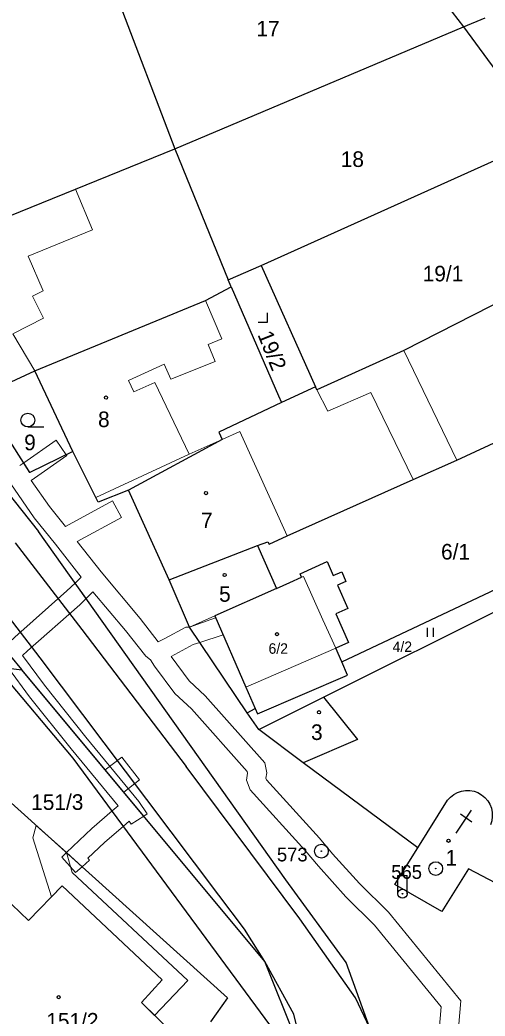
# Model space of a CAD drawing. Extents: x -606517 to -602431, y -1183120 to -1179397.
# Drawn here: x -605471.6 to -605420.9, y -1180870.1 to -1180761.6 of the extents above; entities that cross this region are included whole.
import ezdxf
from ezdxf.enums import TextEntityAlignment as Align

# ---------------------------------------------------------------- set-up
doc = ezdxf.new("R2010")
doc.units = 0
doc.header["$LTSCALE"] = 0.68
for name, color, linetype, lineweight in [('1', 7, 'Continuous', 25), ('13', 7, 'Continuous', 13), ('3', 7, 'Continuous', 25), ('4', 7, 'Continuous', 13), ('5', 7, 'Continuous', 25), ('6', 7, 'Continuous', 25), ('8', 7, 'Continuous', 25)]:
    doc.layers.add(name, color=color, linetype=linetype, lineweight=lineweight)
doc.layers.add('2', color=7, linetype='Continuous')

msp = doc.modelspace()

# ---------------------------------------------------------------- linework, layer by layer
at = {"layer": '1'}
for p, q in [((-605436.71, -1180744.63), (-605423.26, -1180762.37)), ((-605462.45, -1180755.29), (-605454.69, -1180775.65)), ((-605454.69, -1180775.65), (-605423.26, -1180762.37)), ((-605423.26, -1180762.37), (-605420.9, -1180761.38)), ((-605423.26, -1180762.37), (-605414.36, -1180774.43)), ((-605445.31, -1180788.34), (-605414.36, -1180774.43)), ((-605465.54, -1180780.05), (-605454.69, -1180775.65)), ((-605454.69, -1180775.65), (-605448.88, -1180789.92)), ((-605478.02, -1180785.08), (-605465.54, -1180780.05)), ((-605448.88, -1180789.92), (-605445.31, -1180788.34)), ((-605445.31, -1180788.34), (-605439.39, -1180801.56)), ((-605448.57, -1180790.68), (-605448.88, -1180789.92)), ((-605451.36, -1180792.16), (-605448.57, -1180790.68)), ((-605448.57, -1180790.68), (-605443.4, -1180802.52)), ((-605416.71, -1180790.96), (-605429.75, -1180797.61)), ((-605489.67, -1180792.12), (-605469.57, -1180817.3)), ((-605469.96, -1180799.8), (-605451.36, -1180792.16)), ((-605429.75, -1180797.61), (-605439.24, -1180801.88)), ((-605475.85, -1180802.53), (-605469.96, -1180799.8)), ((-605465.83, -1180808.61), (-605469.96, -1180799.8)), ((-605470.51, -1180810.87), (-605475.85, -1180802.53)), ((-605443.4, -1180802.52), (-605443.07, -1180803.28)), ((-605439.39, -1180801.56), (-605443.07, -1180803.28)), ((-605439.24, -1180801.88), (-605439.39, -1180801.56)), ((-605443.07, -1180803.28), (-605449.91, -1180806.48)), ((-605423.96, -1180809.53), (-605412.45, -1180804.22)), ((-605449.91, -1180806.48), (-605449.54, -1180807.29)), ((-605449.54, -1180807.29), (-605459.74, -1180812.8)), ((-605465.83, -1180808.61), (-605470.51, -1180810.87)), ((-605463.31, -1180813.61), (-605465.83, -1180808.61)), ((-605428.74, -1180811.65), (-605423.96, -1180809.53)), ((-605442.47, -1180817.78), (-605428.74, -1180811.65)), ((-605459.74, -1180812.8), (-605463.06, -1180814.11)), ((-605455.32, -1180822.57), (-605459.74, -1180812.8)), ((-605463.06, -1180814.11), (-605463.31, -1180813.61)), ((-605442.62, -1180855.26), (-605469.57, -1180817.3)), ((-605436.52, -1180831.49), (-605406.17, -1180817.2)), ((-605472.09, -1180818.55), (-605464.82, -1180827.99)), ((-605445.7, -1180818.84), (-605444.55, -1180818.43)), ((-605444.55, -1180818.43), (-605444.43, -1180818.69)), ((-605444.43, -1180818.69), (-605442.47, -1180817.78)), ((-605455.32, -1180822.57), (-605445.7, -1180818.84)), ((-605445.7, -1180818.84), (-605443.62, -1180823.51)), ((-605438.49, -1180835.36), (-605405.86, -1180819.07)), ((-605441.05, -1180821.91), (-605438.11, -1180820.59)), ((-605438.11, -1180820.59), (-605437.44, -1180822.11)), ((-605469.39, -1180831.07), (-605476.42, -1180821.94)), ((-605440.88, -1180822.29), (-605441.05, -1180821.91)), ((-605437.44, -1180822.11), (-605436.52, -1180821.7)), ((-605436.52, -1180821.7), (-605436.05, -1180822.75)), ((-605453.1, -1180827.72), (-605455.32, -1180822.57)), ((-605443.62, -1180823.51), (-605442.17, -1180822.87)), ((-605442.17, -1180822.87), (-605440.88, -1180822.29)), ((-605436.05, -1180822.75), (-605436.97, -1180823.16)), ((-605443.62, -1180823.51), (-605450.35, -1180826.5)), ((-605436.97, -1180823.16), (-605435.84, -1180825.69)), ((-605435.84, -1180825.69), (-605437.17, -1180826.28)), ((-605437.17, -1180826.28), (-605435.77, -1180829.41)), ((-605450.35, -1180826.5), (-605446.95, -1180834.26)), ((-605464.82, -1180827.99), (-605453.47, -1180842.89)), ((-605446.81, -1180837.04), (-605453.1, -1180827.72)), ((-605471.38, -1180832.34), (-605473.82, -1180829.44)), ((-605435.77, -1180829.41), (-605437.15, -1180830.03)), ((-605436.52, -1180831.49), (-605437.15, -1180830.03)), ((-605457.76, -1180846.51), (-605469.39, -1180831.07)), ((-605435.88, -1180832.95), (-605436.52, -1180831.49)), ((-605474.17, -1180832.04), (-605471.36, -1180832.38)), ((-605465.77, -1180841.98), (-605474.17, -1180832.04)), ((-605471.36, -1180832.38), (-605471.38, -1180832.34)), ((-605444.9, -1180864.13), (-605471.36, -1180832.38)), ((-605445.69, -1180837.15), (-605435.88, -1180832.95)), ((-605446.95, -1180834.26), (-605445.95, -1180836.57)), ((-605445.56, -1180838.87), (-605438.49, -1180835.36)), ((-605438.49, -1180835.36), (-605434.81, -1180839.95)), ((-605446.81, -1180837.04), (-605445.95, -1180836.57)), ((-605445.56, -1180838.87), (-605446.81, -1180837.04)), ((-605445.95, -1180836.57), (-605445.69, -1180837.15)), ((-605481.78, -1180838.53), (-605448.98, -1180868.1)), ((-605440.72, -1180842.51), (-605445.56, -1180838.87)), ((-605434.81, -1180839.95), (-605440.72, -1180842.51)), ((-605442.62, -1180873.35), (-605465.77, -1180841.98)), ((-605428.22, -1180851.75), (-605440.72, -1180842.51)), ((-605441.08, -1180859.5), (-605453.47, -1180842.89)), ((-605449.91, -1180856.92), (-605457.76, -1180846.51)), ((-605428.22, -1180851.75), (-605424.98, -1180846.58)), ((-605430.72, -1180855.76), (-605428.22, -1180851.75)), ((-605422.7, -1180854.04), (-605425.61, -1180858.7)), ((-605419.72, -1180855.62), (-605422.7, -1180854.04)), ((-605436.03, -1180864.23), (-605442.62, -1180855.26)), ((-605470.64, -1180859.68), (-605466.97, -1180855.88)), ((-605466.97, -1180855.88), (-605456.08, -1180866.15)), ((-605425.61, -1180858.7), (-605430.72, -1180855.76)), ((-605447.12, -1180860.63), (-605449.91, -1180856.92)), ((-605472.46, -1180857.94), (-605470.64, -1180859.68)), ((-605435.03, -1180868.09), (-605441.08, -1180859.5)), ((-605444.9, -1180864.13), (-605447.12, -1180860.63)), ((-605441.2, -1180873.28), (-605444.9, -1180864.13)), ((-605441.75, -1180869.86), (-605444.9, -1180864.13)), ((-605433.45, -1180871.4), (-605436.03, -1180864.23)), ((-605456.08, -1180866.15), (-605458.34, -1180868.59)), ((-605458.34, -1180868.59), (-605455.01, -1180871.88)), ((-605448.98, -1180868.1), (-605450.8, -1180870.69)), ((-605433.45, -1180871.4), (-605435.03, -1180868.09)), ((-605440.96, -1180872.97), (-605441.75, -1180869.86))]:
    msp.add_line(p, q, dxfattribs=at)
msp.add_lwpolyline([(-605424.98, -1180846.58), (-605424.673, -1180846.235), (-605424.311, -1180845.948), (-605423.907, -1180845.726), (-605423.47, -1180845.576), (-605423.014, -1180845.502), (-605422.552, -1180845.507), (-605422.098, -1180845.589), (-605421.665, -1180845.748), (-605421.264, -1180845.978), (-605420.909, -1180846.272), (-605420.608, -1180846.623), (-605420.371, -1180847.019), (-605420.205, -1180847.45), (-605420.114, -1180847.902), (-605420.102, -1180848.364), (-605420.168, -1180848.821), (-605420.31, -1180849.26)], dxfattribs=at)
at = {"layer": '13'}
for points in [[(-605471.17, -1180809.84), (-605470.51, -1180810.87), (-605466.53, -1180808.95), (-605467.63, -1180807.36)], [(-605465.58, -1180822.92), (-605466.46, -1180823.79), (-605472.15, -1180828.8), (-605473.37, -1180829.98), (-605471.38, -1180832.34), (-605471.36, -1180832.38), (-605458.09, -1180848.3), (-605457.73, -1180848.07), (-605458.62, -1180846.7), (-605464.39, -1180839.69), (-605468.92, -1180834.04), (-605471.29, -1180830.82), (-605470.75, -1180830.3), (-605465.06, -1180825.29), (-605464.37, -1180824.62)], [(-605453.1, -1180827.72), (-605451.97, -1180829.39), (-605449.44, -1180828.58), (-605450.26, -1180826.71)], [(-605474.01, -1180830.6), (-605472.83, -1180832.2), (-605470.54, -1180835.3), (-605465.99, -1180840.99), (-605460.88, -1180847.19), (-605461.52, -1180847.74), (-605463.73, -1180849.65), (-605466.52, -1180852.28), (-605464.81, -1180853.83), (-605463.99, -1180853.1), (-605464.19, -1180852.88), (-605462.37, -1180851.17), (-605460.3, -1180849.39), (-605459.68, -1180848.86), (-605459.47, -1180849.19), (-605458.09, -1180848.3), (-605471.36, -1180832.38), (-605471.38, -1180832.34), (-605473.37, -1180829.98)], [(-605462.29, -1180843.27), (-605460.27, -1180845.68), (-605458.55, -1180844.36), (-605460.48, -1180841.88)], [(-605466.52, -1180852.28), (-605469.81, -1180849.32), (-605470.17, -1180850.66), (-605468.13, -1180857.08), (-605466.97, -1180855.88), (-605456.08, -1180866.15), (-605458.34, -1180868.59), (-605456.91, -1180870), (-605453.27, -1180866.22), (-605465.88, -1180854.43)], [(-605464.81, -1180853.83), (-605466.52, -1180852.28), (-605467.03, -1180852.76), (-605465.51, -1180854.46)]]:
    msp.add_lwpolyline(points, close=True, dxfattribs=at)
for points in [[(-605424.05, -1180874.33), (-605423.55, -1180868.42), (-605431.43, -1180858.78), (-605434.58, -1180855.66), (-605437.52, -1180852.41), (-605438.95, -1180850.69), (-605444.7, -1180844.36), (-605444.77, -1180844.17), (-605444.67, -1180843.58), (-605444.91, -1180842.49), (-605451.4, -1180835.19), (-605453.15, -1180833.58), (-605455.11, -1180830.93), (-605452.7, -1180829.62), (-605451.97, -1180829.39), (-605453.1, -1180827.72), (-605453.52, -1180827.74), (-605455.79, -1180828.98), (-605456.5, -1180829.32), (-605458.48, -1180826.79), (-605462.73, -1180821.72), (-605465.33, -1180818.39), (-605460.53, -1180815.77), (-605461.51, -1180813.97), (-605466.62, -1180816.76), (-605468.37, -1180814.59), (-605470.34, -1180811.74), (-605466.47, -1180809.04), (-605466.53, -1180808.95), (-605470.51, -1180810.87), (-605471.17, -1180809.84), (-605471.59, -1180810.13)], [(-605472.57, -1180812.13), (-605470.03, -1180815.81), (-605467.71, -1180818.69), (-605464.92, -1180822.27), (-605465.58, -1180822.92), (-605464.37, -1180824.62), (-605463.62, -1180823.88), (-605460.08, -1180828.09), (-605457.88, -1180830.89), (-605457.36, -1180831.3), (-605456.9, -1180831.97), (-605454.69, -1180834.96), (-605452.88, -1180836.63), (-605446.81, -1180843.46), (-605446.77, -1180843.64), (-605446.89, -1180844.39), (-605446.48, -1180845.46), (-605440.49, -1180852.05), (-605439.06, -1180853.77), (-605436.06, -1180857.08), (-605432.95, -1180860.18)], [(-605432.95, -1180860.18), (-605425.67, -1180869.08), (-605426.14, -1180874.57)]]:
    msp.add_lwpolyline(points, dxfattribs=at)
at = {"layer": '3'}
for p, q in [((-605470.723, -1180805.93), (-605468.973, -1180805.93)), ((-605427.172, -1180828.79), (-605427.172, -1180827.785)), ((-605426.502, -1180828.79), (-605426.502, -1180827.785))]:
    msp.add_line(p, q, dxfattribs=at)
msp.add_lwpolyline([(-605445.621, -1180794.51), (-605444.62, -1180794.51), (-605444.62, -1180793.51)], dxfattribs=at)
msp.add_circle((-605470.7229, -1180805.1798), 0.75, dxfattribs=at)
at = {"layer": '4'}
for p, q in [((-605465.54, -1180780.05), (-605463.69, -1180784.47)), ((-605463.69, -1180784.47), (-605470.68, -1180787.32)), ((-605470.68, -1180787.32), (-605469.04, -1180791.11)), ((-605469.04, -1180791.11), (-605470.23, -1180791.68)), ((-605470.23, -1180791.68), (-605469.01, -1180794.08)), ((-605451.36, -1180792.16), (-605449.58, -1180796.33)), ((-605469.01, -1180794.08), (-605472.36, -1180795.78)), ((-605469.96, -1180799.8), (-605472.36, -1180795.78)), ((-605449.58, -1180796.33), (-605451.08, -1180796.96)), ((-605451.08, -1180796.96), (-605450.31, -1180798.81)), ((-605423.96, -1180809.53), (-605429.75, -1180797.61)), ((-605459.76, -1180800.85), (-605455.87, -1180799.09)), ((-605455.87, -1180799.09), (-605455.13, -1180800.73)), ((-605450.31, -1180798.81), (-605455.13, -1180800.73)), ((-605459.18, -1180802.12), (-605459.76, -1180800.85)), ((-605456.89, -1180801.09), (-605459.18, -1180802.12)), ((-605453.15, -1180808.9), (-605456.89, -1180801.09)), ((-605439.24, -1180801.88), (-605438.02, -1180804.2)), ((-605438.02, -1180804.2), (-605433.35, -1180802.16)), ((-605433.35, -1180802.16), (-605428.74, -1180811.65)), ((-605449.54, -1180807.29), (-605447.6, -1180806.42)), ((-605447.6, -1180806.42), (-605442.47, -1180817.78)), ((-605453.15, -1180808.9), (-605449.54, -1180807.29)), ((-605463.31, -1180813.61), (-605453.15, -1180808.9)), ((-605440.69, -1180822.21), (-605440.88, -1180822.29)), ((-605438.59, -1180826.92), (-605440.69, -1180822.21)), ((-605450.35, -1180826.5), (-605453.1, -1180827.72)), ((-605437.15, -1180830.03), (-605438.59, -1180826.92)), ((-605446.95, -1180834.26), (-605437.15, -1180830.03))]:
    msp.add_line(p, q, dxfattribs=at)
at = {"layer": '5'}
for p, q in [((-605422.402, -1180847.663), (-605424.08, -1180850.15)), ((-605423.585, -1180848.073), (-605422.34, -1180848.913))]:
    msp.add_line(p, q, dxfattribs=at)
for centre in [(-605462.1968, -1180802.7292), (-605451.3068, -1180813.1292), (-605449.2768, -1180822.0492), (-605443.5668, -1180828.4892), (-605438.9868, -1180836.9892), (-605424.8768, -1180850.9892), (-605467.3568, -1180868.0192)]:
    msp.add_circle(centre, 0.175, dxfattribs=at)
at = {"layer": '6'}
for p, q in [((-605429.89, -1180854.756), (-605429.89, -1180853.756)), ((-605430.39, -1180854.756), (-605429.39, -1180854.756)), ((-605430.39, -1180856.756), (-605430.39, -1180854.756)), ((-605429.39, -1180856.756), (-605429.39, -1180854.756))]:
    msp.add_line(p, q, dxfattribs=at)
for radius in [0.5, 0.0303]:
    msp.add_circle((-605429.89, -1180856.7576), radius, dxfattribs=at)
at = {"layer": '8'}
for centre, radius in [((-605438.73, -1180852.1198), 0.75), ((-605438.73, -1180852.1198), 0.03), ((-605426.27, -1180854.0198), 0.75), ((-605426.27, -1180854.0198), 0.03)]:
    msp.add_circle(centre, radius, dxfattribs=at)

# ---------------------------------------------------------------- texts
at = {"layer": '2'}
for s, height, p in [('17', 1.7, (-605445.81, -1180763.405)), ('18', 1.7, (-605436.62, -1180777.615)), ('19/1', 1.7, (-605427.69, -1180790.075)), ('8', 1.7, (-605463.07, -1180805.945)), ('9', 1.7, (-605471.12, -1180808.465)), ('7', 1.7, (-605451.84, -1180816.945)), ('6/1', 1.7, (-605425.69, -1180820.365)), ('5', 1.7, (-605449.88, -1180824.965)), ('6/2', 1.14, (-605444.49, -1180830.625)), ('3', 1.7, (-605439.86, -1180840.015)), ('1', 1.7, (-605425.2, -1180853.695)), ('151/2', 1.7, (-605468.71, -1180871.445))]:
    msp.add_text(s, height=height, dxfattribs=at).set_placement(p)
msp.add_text('19/2', height=1.7, rotation=292, dxfattribs=at).set_placement((-605444.8883, -1180797.9211), align=Align.CENTER)
for s, height, p in [('4/2', 1.14, (-605429.909, -1180830.43)), ('151/3', 1.7, (-605467.51, -1180847.625))]:
    msp.add_text(s, height=height, dxfattribs=at).set_placement(p, align=Align.CENTER)
at = {"layer": '8'}
for s, p in [('573', (-605440.229, -1180853.237)), ('565', (-605427.769, -1180855.137))]:
    msp.add_text(s, height=1.5, dxfattribs=at).set_placement(p, align=Align.RIGHT)

doc.saveas('drawing.dxf')
